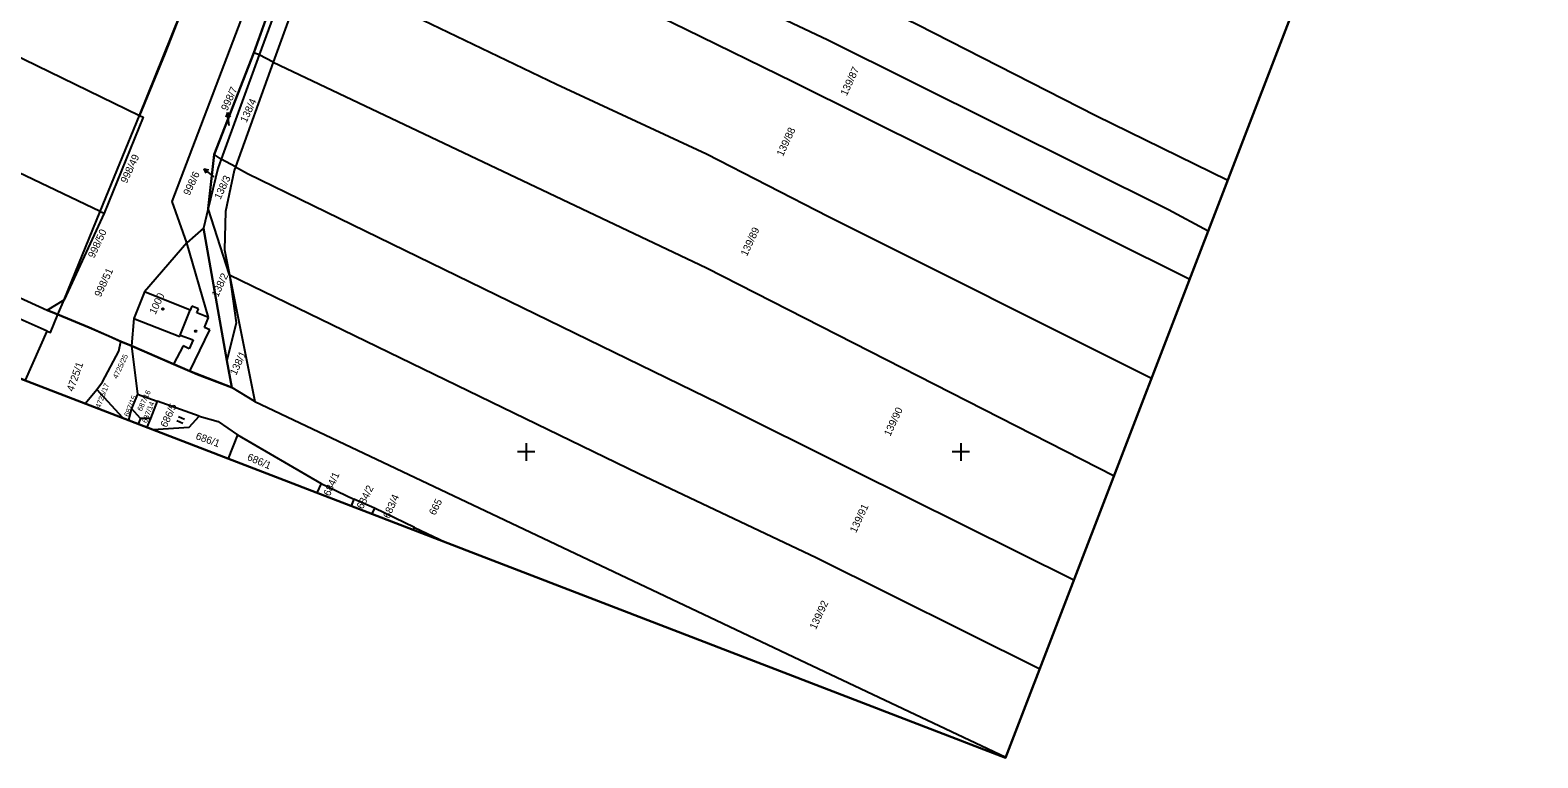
# Model space of a CAD drawing. Extents: x -755344 to -754412, y -1162670 to -1161477.
# Drawn here: x -755014.1 to -754667.3, y -1162670.3 to -1162503 of the extents above; entities that cross this region are included whole.
import ezdxf

# ---------------------------------------------------------------- set-up
doc = ezdxf.new("R2010")
doc.units = 0
for name, color, linetype in [('Formát', 7, 'Continuous'), ('Katastrální hranice', 7, 'Continuous'), ('Síť', 7, 'Continuous'), ('Vrstva 53', 7, 'Continuous'), ('Vrstva 55', 7, 'Continuous'), ('Vrstva 56', 7, 'Continuous'), ('Vrstva 57', 7, 'Continuous'), ('Vrstva 58', 7, 'Continuous'), ('Vrstva 59', 7, 'Continuous')]:
    doc.layers.add(name, color=color, linetype=linetype)

msp = doc.modelspace()

# ---------------------------------------------------------------- linework, layer by layer
at = {"layer": 'Formát'}
msp.add_line((-755344.08, -1162456.97), (-754789.71, -1162670.32), dxfattribs=at)
msp.add_lwpolyline([(-754488.01, -1161886.37), (-754789.71, -1162670.32), (-755344.08, -1162456.97), (-755042.37, -1161673.02)], close=True, dxfattribs=at)
for points in [[(-755344.08, -1162456.97), (-754789.71, -1162670.32), (-754488.01, -1161886.37), (-755042.37, -1161673.02)], [(-755344.08, -1162456.97), (-754789.71, -1162670.32), (-754488.01, -1161886.37), (-755042.37, -1161673.02)], [(-754789.71, -1162670.32), (-754488.01, -1161886.37), (-755042.37, -1161673.02), (-755344.08, -1162456.97)]]:
    msp.add_lwpolyline(points, dxfattribs=at)
at = {"layer": 'Katastrální hranice'}
for p, q in [((-754961.39, -1162508.73), (-754970.12, -1162532.66)), ((-754970.12, -1162532.66), (-754970.91, -1162534.82)), ((-754970.91, -1162534.82), (-754973.09, -1162544.04)), ((-755064.06, -1162542.65), (-755010.16, -1162567.43)), ((-754973.09, -1162544.04), (-754974.17, -1162548.58)), ((-754968.81, -1162578.95), (-754974.17, -1162548.58)), ((-755010.16, -1162567.43), (-755007.72, -1162568.42)), ((-754996.07, -1162573.33), (-754993.17, -1162574.58)), ((-754993.17, -1162574.58), (-754990.79, -1162575.62)), ((-754967.71, -1162585.17), (-754968.81, -1162578.95))]:
    msp.add_line(p, q, dxfattribs=at)
for points in [[(-754953.13, -1162486.42), (-754957.12, -1162497.02), (-754961.39, -1162508.73)], [(-755007.72, -1162568.42), (-755000.46, -1162571.42), (-754996.07, -1162573.33)], [(-754990.79, -1162575.62), (-754981.12, -1162579.81), (-754977.36, -1162581.44), (-754975.59, -1162582.21), (-754967.71, -1162585.17)]]:
    msp.add_lwpolyline(points, dxfattribs=at)
at = {"layer": 'Síť'}
for points in [[(-754900, -1162598), (-754900, -1162600), (-754900, -1162602)], [(-754800, -1162598), (-754800, -1162600), (-754800, -1162602)], [(-754898, -1162600), (-754900, -1162600), (-754902, -1162600)], [(-754798, -1162600), (-754800, -1162600), (-754802, -1162600)]]:
    msp.add_lwpolyline(points, dxfattribs=at)
at = {"layer": 'Vrstva 53'}
msp.add_lwpolyline([(-754954.58, -1162485.64), (-754962.59, -1162508.22), (-754971.75, -1162531.64), (-754973.09, -1162544.04), (-754974.17, -1162548.58), (-754968.81, -1162578.95), (-754967.71, -1162585.17), (-754977.36, -1162581.44), (-754990.79, -1162575.62), (-754993.17, -1162574.58), (-755000.46, -1162571.42), (-755007.72, -1162568.42), (-755010.16, -1162567.43), (-755006.25, -1162565.05), (-754997.93, -1162544.71), (-754988.9, -1162522.63), (-754979.63, -1162499.65)], dxfattribs=at)
at = {"layer": 'Vrstva 55'}
for p, q in [((-754962.59, -1162508.22), (-754954.58, -1162485.64)), ((-754950.07, -1162488.05), (-754958.17, -1162510.4)), ((-754997.93, -1162544.71), (-755083.94, -1162503.85)), ((-754971.75, -1162531.64), (-754962.59, -1162508.22)), ((-754961.39, -1162508.73), (-754970.12, -1162532.66)), ((-754961.39, -1162508.73), (-754970.12, -1162532.66)), ((-754961.39, -1162508.73), (-754962.59, -1162508.22)), ((-754958.17, -1162510.4), (-754961.39, -1162508.73)), ((-754958.17, -1162510.4), (-754966.87, -1162534.43)), ((-754997.93, -1162544.71), (-754988.9, -1162522.63)), ((-754973.09, -1162544.04), (-754971.75, -1162531.64)), ((-754970.12, -1162532.66), (-754971.75, -1162531.64)), ((-754970.12, -1162532.66), (-754970.91, -1162534.82)), ((-754970.12, -1162532.66), (-754970.91, -1162534.82)), ((-754966.87, -1162534.43), (-754970.12, -1162532.66)), ((-754970.91, -1162534.82), (-754973.09, -1162544.04)), ((-754970.91, -1162534.82), (-754973.09, -1162544.04)), ((-755064.06, -1162542.65), (-755010.16, -1162567.43)), ((-755064.06, -1162542.65), (-755010.16, -1162567.43)), ((-755006.25, -1162565.05), (-754997.93, -1162544.71)), ((-754997.07, -1162545.12), (-755006.25, -1162565.05)), ((-754997.93, -1162544.71), (-754997.07, -1162545.12)), ((-754973.09, -1162544.04), (-754974.17, -1162548.58)), ((-754973.09, -1162544.04), (-754974.17, -1162548.58)), ((-754968.19, -1162559.28), (-754973.09, -1162544.04)), ((-754969.15, -1162544.73), (-754969.34, -1162553.5)), ((-754974.17, -1162548.58), (-754978.01, -1162551.88)), ((-754968.81, -1162578.95), (-754974.17, -1162548.58)), ((-754968.81, -1162578.95), (-754974.17, -1162548.58)), ((-754969.34, -1162553.5), (-754968.19, -1162559.28)), ((-754968.19, -1162559.28), (-754962.36, -1162588.4)), ((-755010.18, -1162572.23), (-755030.16, -1162563.38)), ((-755010.16, -1162567.43), (-755006.25, -1162565.05)), ((-755010.16, -1162567.43), (-755007.72, -1162568.42)), ((-755010.16, -1162567.43), (-755007.72, -1162568.42)), ((-755007.72, -1162568.42), (-755006.25, -1162565.05)), ((-754996.07, -1162573.33), (-754993.17, -1162574.58)), ((-754996.07, -1162573.33), (-754993.17, -1162574.58)), ((-754993.17, -1162574.58), (-754990.79, -1162575.62)), ((-754993.17, -1162574.58), (-754990.79, -1162575.62)), ((-754990.79, -1162575.62), (-754989.39, -1162586.71)), ((-754967.71, -1162585.17), (-754968.81, -1162578.95)), ((-754967.71, -1162585.17), (-754968.81, -1162578.95)), ((-754962.36, -1162588.4), (-754967.71, -1162585.17)), ((-754992.76, -1162592.18), (-754998.76, -1162585.67)), ((-754989.39, -1162586.71), (-754990.72, -1162590.03)), ((-754989.39, -1162586.71), (-754984.84, -1162588.34)), ((-754984.84, -1162588.34), (-754986.41, -1162592.29)), ((-754975.18, -1162591.8), (-754984.84, -1162588.34)), ((-754990.72, -1162590.03), (-754991.46, -1162592.68)), ((-754988.68, -1162592.32), (-754990.72, -1162590.03)), ((-754986.41, -1162592.29), (-754988.68, -1162592.32)), ((-754986.41, -1162592.29), (-754987.22, -1162594.31)), ((-754966.39, -1162596.08), (-754968.55, -1162601.49)), ((-754966.39, -1162596.08), (-754947.12, -1162607.26)), ((-754947.12, -1162607.26), (-754948.09, -1162609.37)), ((-754947.12, -1162607.26), (-754939.59, -1162610.85)), ((-754934.83, -1162612.91), (-754939.59, -1162610.85)), ((-754934.83, -1162612.91), (-754935.46, -1162614.23)), ((-754925.64, -1162617.33), (-754934.83, -1162612.91)), ((-754925.9, -1162617.91), (-754925.64, -1162617.33)), ((-754925.64, -1162617.33), (-754918.52, -1162620.75))]:
    msp.add_line(p, q, dxfattribs=at)
for points in [[(-754978.01, -1162551.88), (-754981.37, -1162542.41), (-754930.02, -1162407.36), (-754870.17, -1162267.96), (-754836.4, -1162183.6), (-754824.89, -1162157.4), (-754808.97, -1162117.64), (-754790.52, -1162068.93), (-754761.32, -1161999.17), (-754754.27, -1161988.55)], [(-754932.95, -1162442.03), (-754895.12, -1162460.64), (-754826.15, -1162493.85), (-754809.95, -1162501.75), (-754768.98, -1162522.66), (-754738.59, -1162537.48)], [(-754743.11, -1162549.24), (-754752.28, -1162544.32), (-754830.58, -1162505.29), (-754871.24, -1162486.05), (-754935.11, -1162454.22), (-754937.16, -1162453.22)], [(-754941.53, -1162464.82), (-754934.04, -1162468.42), (-754863.22, -1162502.76), (-754838.48, -1162514.89), (-754806.14, -1162530.97), (-754747.37, -1162560.3)], [(-755091.61, -1162473.83), (-755054.02, -1162490.91), (-754988.9, -1162522.63)], [(-754953.13, -1162486.42), (-754957.12, -1162497.02), (-754961.39, -1162508.73)], [(-754953.13, -1162486.42), (-754957.12, -1162497.02), (-754961.39, -1162508.73)], [(-754950.07, -1162488.05), (-754944.78, -1162490.56), (-754893.03, -1162515.45), (-754858.48, -1162531.49), (-754830.45, -1162545.87), (-754756.13, -1162583.06)], [(-754979.63, -1162499.65), (-754983.12, -1162508.48), (-754988.9, -1162522.63)], [(-754958.17, -1162510.4), (-754858.48, -1162557.7), (-754764.77, -1162605.5)], [(-754988.9, -1162522.63), (-754988.1, -1162523.02), (-754997.07, -1162545.12)], [(-754966.87, -1162534.43), (-754967.17, -1162535.26), (-754969.15, -1162544.73)], [(-754966.87, -1162534.43), (-754964.08, -1162535.95), (-754855.65, -1162588.75), (-754824.76, -1162604.15), (-754773.98, -1162629.43)], [(-754978.01, -1162551.88), (-754987.73, -1162563.16), (-754990.19, -1162569.34), (-754990.79, -1162575.62)], [(-754968.19, -1162559.28), (-754966.66, -1162570.34), (-754968.81, -1162578.95)], [(-754968.19, -1162559.28), (-754874.06, -1162604.93), (-754833.26, -1162624.24), (-754781.84, -1162649.85)], [(-755010.18, -1162572.23), (-755009.42, -1162572.57), (-755007.72, -1162568.42)], [(-755007.72, -1162568.42), (-755000.46, -1162571.42), (-754996.07, -1162573.33)], [(-755007.72, -1162568.42), (-755000.46, -1162571.42), (-754996.07, -1162573.33)], [(-755034.91, -1162575.76), (-755015.17, -1162583.46), (-755010.18, -1162572.23)], [(-754998.76, -1162585.67), (-754997.42, -1162583.88), (-754993.66, -1162576.85), (-754993.17, -1162574.58)], [(-754990.79, -1162575.62), (-754981.12, -1162579.81), (-754977.36, -1162581.44), (-754975.59, -1162582.21), (-754967.71, -1162585.17)], [(-754990.79, -1162575.62), (-754981.12, -1162579.81), (-754977.36, -1162581.44), (-754975.59, -1162582.21), (-754967.71, -1162585.17)], [(-755001.44, -1162588.84), (-754998.76, -1162585.67)], [(-754962.36, -1162588.4), (-754835.57, -1162648.45), (-754789.66, -1162670.19)], [(-754985.88, -1162594.82), (-754977.52, -1162594.32), (-754975.18, -1162591.8)], [(-754975.18, -1162591.8), (-754970.84, -1162592.98), (-754966.39, -1162596.08)], [(-754988.68, -1162592.32), (-754989.2, -1162593.55)], [(-754939.59, -1162610.85), (-754940.26, -1162612.38)]]:
    msp.add_lwpolyline(points, dxfattribs=at)
at = {"layer": 'Vrstva 56'}
for p, q in [((-754973.06, -1162569.09), (-754978.01, -1162551.88)), ((-754977.24, -1162567.4), (-754987.73, -1162563.16)), ((-754979.54, -1162573.11), (-754977.24, -1162567.4)), ((-754976.86, -1162566.48), (-754977.24, -1162567.4)), ((-754975.36, -1162567.08), (-754976.86, -1162566.48)), ((-754975.74, -1162568.01), (-754975.36, -1162567.08)), ((-754973.06, -1162569.09), (-754975.74, -1162568.01)), ((-754990.19, -1162569.34), (-754979.67, -1162573.44)), ((-754974, -1162571.4), (-754973.06, -1162569.09)), ((-754972.76, -1162571.89), (-754974, -1162571.4)), ((-754979.67, -1162573.44), (-754979.54, -1162573.11)), ((-754979.54, -1162573.11), (-754976.57, -1162574.2)), ((-754976.57, -1162574.2), (-754977.49, -1162576.26)), ((-754977.36, -1162581.44), (-754972.76, -1162571.89)), ((-754978.86, -1162575.61), (-754981.12, -1162579.81)), ((-754977.49, -1162576.26), (-754978.86, -1162575.61))]:
    msp.add_line(p, q, dxfattribs=at)
at = {"layer": 'Vrstva 57'}
for p, q in [((-754968.69, -1162521.99), (-754969.05, -1162523.05)), ((-754968.3, -1162524.97), (-754968.69, -1162521.99)), ((-754968.69, -1162521.99), (-754968.06, -1162522.92)), ((-754971.72, -1162536.71), (-754974.14, -1162534.93)), ((-754974.14, -1162534.93), (-754973.04, -1162535.12)), ((-754974.14, -1162534.93), (-754973.63, -1162535.93))]:
    msp.add_line(p, q, dxfattribs=at)
at = {"layer": 'Vrstva 58'}
for p, q in [((-754978.55, -1162592.56), (-754979.91, -1162591.93)), ((-754978.97, -1162593.47), (-754980.33, -1162592.84))]:
    msp.add_line(p, q, dxfattribs=at)
at = {"layer": 'Vrstva 59'}
for centre in [(-754983.54, -1162567.14), (-754976.01, -1162572.23)]:
    msp.add_circle(centre, 0.175, dxfattribs=at)

# ---------------------------------------------------------------- texts
at = {"layer": 'Vrstva 57'}
for s, height, rotation, p in [('139/87', 1.7, 65, (-754826.26, -1162518.26)), ('998/7', 1.7, 65, (-754968.73, -1162521.71)), ('138/4', 1.7, 65, (-754964.32, -1162524.42)), ('139/88', 1.7, 65, (-754840.93, -1162532.18)), ('998/49', 1.7, 65, (-754991.84, -1162538.37)), ('998/6', 1.7, 65, (-754977.41, -1162541.17)), ('138/3', 1.7, 65, (-754970.29, -1162542.08)), ('998/50', 1.7, 65, (-754999.33, -1162555.58)), ('139/89', 1.7, 65, (-754849.2, -1162555.13)), ('998/51', 1.7, 65, (-754997.85, -1162564.52)), ('138/2', 1.7, 65, (-754970.86, -1162564.54)), ('1000', 1.7, 65, (-754985.24, -1162568.52)), ('4725/25', 1.2, 65, (-754994.04, -1162583.3)), ('138/1', 1.7, 65, (-754966.7, -1162582.5)), ('4725/1', 1.7, 70.5369, (-755004.13, -1162586.24)), ('4725/17', 1.2, 69, (-754997.97, -1162590.06)), ('687/15', 1.2, 68, (-754991.41, -1162592.01)), ('687/16', 1.2, 65, (-754988.41, -1162590.73)), ('687/14', 1.2, 68.8604, (-754987.26, -1162593.45)), ('686/5', 1.7, 65, (-754982.68, -1162594.52)), ('139/90', 1.7, 65, (-754816.24, -1162596.52)), ('686/1', 1.7, 340.0537, (-754976.13, -1162597)), ('686/1', 1.7, 336.8417, (-754964.3, -1162601.79)), ('684/1', 1.7, 66.2099, (-754945.15, -1162610.29)), ('684/2', 1.7, 63, (-754937.58, -1162613.28)), ('683/4', 1.7, 66.3452, (-754931.44, -1162615.43)), ('665', 1.7, 63.2827, (-754920.93, -1162614.7)), ('139/91', 1.7, 65, (-754824.11, -1162618.74)), ('139/92', 1.7, 65, (-754833.36, -1162640.96))]:
    msp.add_text(s, height=height, rotation=rotation, dxfattribs=at).set_placement(p)

doc.saveas('drawing.dxf')
